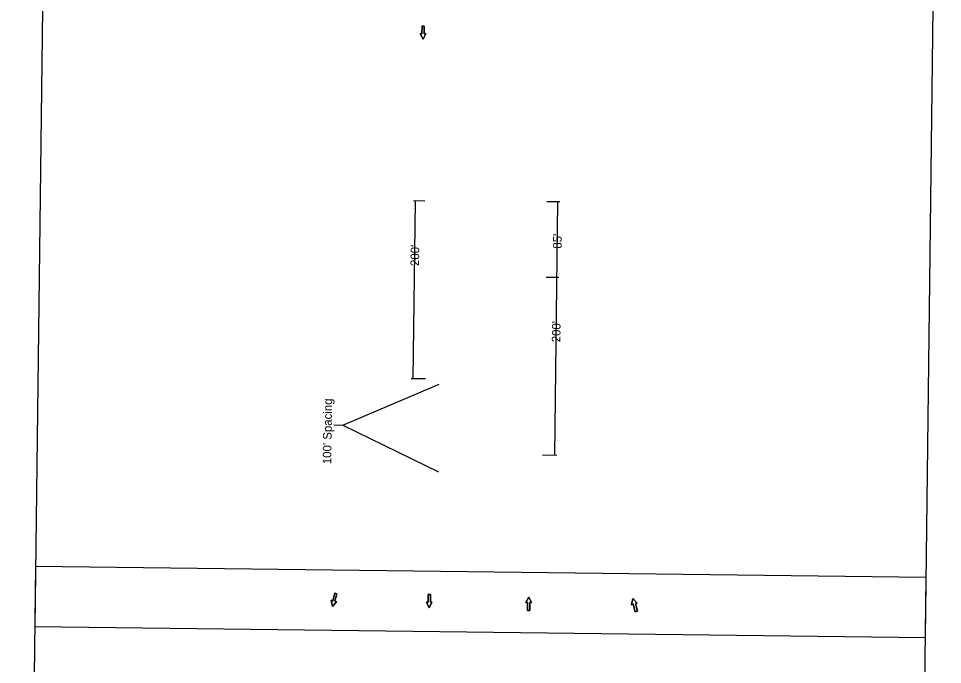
# Model space of a CAD drawing. Extents: x 4959127 to 4960275, y 3872379 to 3884458.
# Drawn here: x 4959164 to 4960201, y 3876849 to 3877574 of the extents above; entities that cross this region are included whole.
import ezdxf

# ---------------------------------------------------------------- set-up
doc = ezdxf.new("R2010")
doc.units = 0
for name, color, linetype in [('Level 2', 7, 'Continuous'), ('Level 5', 7, 'Continuous'), ('NamedBoundary', 7, 'Continuous'), ('SheetText', 7, 'Continuous')]:
    doc.layers.add(name, color=color, linetype=linetype)

msp = doc.modelspace()

# ---------------------------------------------------------------- linework, layer by layer
at = {"layer": 'Level 2'}
for points in [[(4959616.8, 3877565.2), (4959619.3, 3877565.1), (4959619.2, 3877556.4), (4959621.1, 3877556.4), (4959617.9, 3877550.2), (4959614.8, 3877556.4), (4959616.7, 3877556.4)], [(4959518.7, 3876928.6), (4959521.1, 3876928), (4959518.9, 3876919.5), (4959520.7, 3876919), (4959516.1, 3876913.8), (4959514.7, 3876920.6), (4959516.5, 3876920.1)], [(4959623.7, 3876927.2), (4959626.2, 3876927.2), (4959626.1, 3876918.4), (4959627.9, 3876918.4), (4959624.7, 3876912.2), (4959621.7, 3876918.5), (4959623.6, 3876918.5)], [(4959737.7, 3876909.3), (4959735.2, 3876909.3), (4959735.3, 3876918.1), (4959733.4, 3876918.1), (4959736.7, 3876924.3), (4959739.7, 3876918), (4959737.8, 3876918)], [(4959737.7, 3876909.3), (4959735.2, 3876909.3), (4959735.3, 3876918.1), (4959733.4, 3876918.1), (4959736.7, 3876924.3), (4959739.7, 3876918), (4959737.8, 3876918)], [(4959858.6, 3876908.4), (4959856.2, 3876907.8), (4959853.9, 3876916.2), (4959852.1, 3876915.7), (4959853.5, 3876922.6), (4959858.2, 3876917.4), (4959856.4, 3876916.9)]]:
    msp.add_lwpolyline(points, close=True, dxfattribs=at)
at = {"layer": 'Level 5'}
for points in [[(4959616.7, 3877556.4), (4959614.8, 3877556.4), (4959617.9, 3877550.2), (4959621.1, 3877556.4), (4959619.2, 3877556.4), (4959619.3, 3877565.1), (4959616.8, 3877565.2), (4959616.7, 3877556.4)], [(4959516.5, 3876920.1), (4959514.7, 3876920.6), (4959516.1, 3876913.8), (4959520.7, 3876919), (4959518.9, 3876919.5), (4959521.1, 3876928), (4959518.7, 3876928.6), (4959516.5, 3876920.1)], [(4959623.6, 3876918.5), (4959621.7, 3876918.5), (4959624.7, 3876912.2), (4959627.9, 3876918.4), (4959626.1, 3876918.4), (4959626.2, 3876927.2), (4959623.7, 3876927.2), (4959623.6, 3876918.5)], [(4959737.8, 3876918), (4959739.7, 3876918), (4959736.7, 3876924.3), (4959733.4, 3876918.1), (4959735.3, 3876918.1), (4959735.2, 3876909.3), (4959737.7, 3876909.3), (4959737.8, 3876918)], [(4959737.8, 3876918), (4959739.7, 3876918), (4959736.7, 3876924.3), (4959733.4, 3876918.1), (4959735.3, 3876918.1), (4959735.2, 3876909.3), (4959737.7, 3876909.3), (4959737.8, 3876918)], [(4959856.4, 3876916.9), (4959858.2, 3876917.4), (4959853.5, 3876922.6), (4959852.1, 3876915.7), (4959853.9, 3876916.2), (4959856.2, 3876907.8), (4959858.6, 3876908.4), (4959856.4, 3876916.9)]]:
    msp.add_lwpolyline(points, dxfattribs=at)
at = {"layer": 'NamedBoundary'}
for points in [[(4959182, 3876891.1), (4960182, 3876878.8), (4960201.2, 3878446.2), (4959201.3, 3878458.5)], [(4959163.7, 3875391.2), (4960163.6, 3875379), (4960182.8, 3876946.3), (4959182.9, 3876958.6)]]:
    msp.add_lwpolyline(points, close=True, dxfattribs=at)
at = {"layer": 'SheetText'}
for p, q in [((4959607, 3877169.1), (4959609.5, 3877368.8)), ((4959619.8, 3877368.7), (4959607.1, 3877368.8)), ((4959756.8, 3877368.3), (4959771.5, 3877368.1)), ((4959765.7, 3877083.5), (4959769.2, 3877368.2)), ((4959756.1, 3877283.3), (4959770.5, 3877283.1)), ((4959620.5, 3877169), (4959604.7, 3877169.2)), ((4959527.8, 3877117.3), (4959635.9, 3877163.3)), ((4959752.2, 3877083.7), (4959768, 3877083.5))]:
    msp.add_line(p, q, dxfattribs=at)
msp.add_lwpolyline([(4959517.8, 3877117.4), (4959527.8, 3877117.3), (4959635.4, 3877064.8)], dxfattribs=at)

# ---------------------------------------------------------------- texts
for s, rotation, p in [("85'", 89.2975, (4959773.4, 3877315.2)), ("200'", 89.2975, (4959613.4, 3877295.7)), ("200'", 89.2975, (4959772.1, 3877210.1)), ("100' Spacing", 89.2908, (4959514.8, 3877073.3))]:
    msp.add_text(s, height=9.6, rotation=rotation, dxfattribs=at).set_placement(p)

doc.saveas('drawing.dxf')
